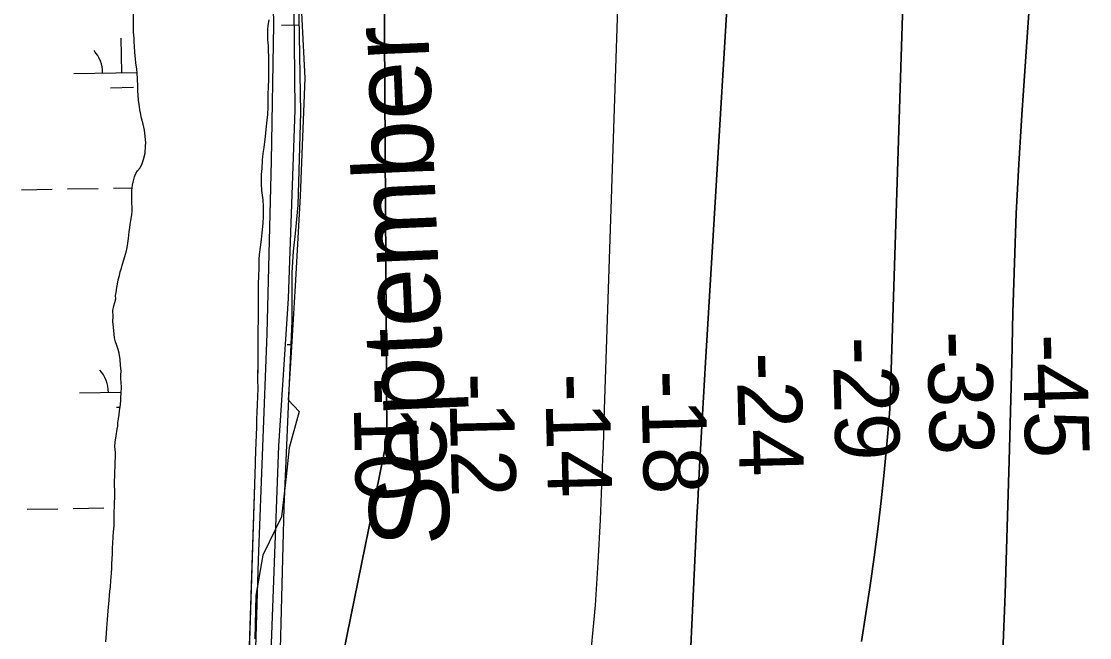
# Model space of a CAD drawing. Extents: x 3925854 to 3964121, y 224593 to 250589.
# Drawn here: x 3942489 to 3943602, y 239849 to 240491 of the extents above; entities that cross this region are included whole.
import ezdxf

# ---------------------------------------------------------------- set-up
doc = ezdxf.new("R2010")
doc.units = 0
for name, color, linetype in [('V-RIVR-EDGE', 7, 'Continuous'), ('V-RIVR-IDEN', 7, 'Continuous'), ('V-RIVR-JETY', 7, 'Continuous'), ('V-RIVR-RANG', 7, 'Continuous'), ('V-TOPO-DPTH', 7, 'Continuous'), ('V-TOPO-MINR', 7, 'Continuous'), ('V-TOPO-SHOR', 7, 'Continuous'), ('V-WETL-SWMP', 7, 'Continuous')]:
    doc.layers.add(name, color=color, linetype=linetype)

msp = doc.modelspace()

# ---------------------------------------------------------------- linework, layer by layer
at = {"layer": 'V-RIVR-EDGE'}
msp.add_lwpolyline([(3942781.233, 241173.826), (3942770.996, 241115.474), (3942773.043, 241052.004), (3942781.233, 241003.889), (3942775.091, 240945.538), (3942767.925, 240925.063), (3942763.83, 240896.399), (3942762.806, 240867.736), (3942765.877, 240813.479), (3942777.138, 240788.91), (3942776.115, 240597.475), (3942781.233, 240493.057), (3942784.304, 240431.634), (3942779.186, 240308.789), (3942774.067, 240215.631), (3942769.972, 240146.018), (3942766.901, 240096.88), (3942778.162, 240084.595), (3942767.925, 240046.718), (3942764.854, 240017.03), (3942759.735, 239975.058), (3942740.285, 239935.133), (3942733.119, 239893.161), (3942732.095, 239848.118)], dxfattribs=at)
at = {"layer": 'V-RIVR-JETY'}
for points in [[(3942501.881, 238496.007), (3942530.957, 238578.48), (3942555.82, 238617.728), (3942596.956, 238684.087), (3942673.397, 238798.99), (3942694.77, 238864.612), (3942700.089, 238923.816), (3942705.303, 239063.915), (3942714.359, 239211.498), (3942718.996, 239386.408), (3942726.512, 239566.929), (3942728.732, 239690.128), (3942735.923, 239929.912), (3942744.955, 240165.915), (3942749.64, 240345.527), (3942752.055, 240487.535), (3942748.285, 240668.175), (3942752.491, 240801.701), (3942752.37, 240880.714), (3942745.499, 240943.807), (3942747.22, 241019.038), (3942753.828, 241112.093), (3942757.154, 241251.271)], [(3942538.571, 238553.806), (3942560.622, 238594.024), (3942630.365, 238697.71), (3942697.234, 238796.723), (3942709.735, 238822.929), (3942715.631, 238847.327), (3942722.113, 238928.151), (3942724.245, 239042.886), (3942729.685, 239204.617), (3942737.78, 239350.33), (3942741.958, 239481.033), (3942746.566, 239653.121), (3942749.476, 239843.095), (3942757.257, 240049.011), (3942767.313, 240202.23), (3942774.055, 240398.75), (3942772.697, 240539.858), (3942769.602, 240695.094), (3942767.962, 240808.926), (3942767.018, 240899.237), (3942767.151, 241002.704), (3942769.979, 241093.915), (3942774.399, 241248.132)]]:
    msp.add_lwpolyline(points, dxfattribs=at)
at = {"layer": 'V-TOPO-DPTH'}
for points in [[(3942983.62, 238887.801), (3942658.91, 239021.11), (3942869.48, 240055.28), (3942865.529, 240782.275), (3942865.271, 240811.75), (3942864.883, 240841.222), (3942864.3, 240870.691), (3942863.587, 240900.157), (3942843.55, 241628.53), (3943150.608, 241695.11)], [(3943571.432, 241621.688), (3943574.45, 241120.853), (3943574.275, 241081.301), (3943573.548, 241041.766), (3943571.995, 241002.255), (3943569.89, 240962.759), (3943564.953, 240885.365), (3943564.898, 240884.579), (3943564.764, 240883.009), (3943564.409, 240879.085), (3943531.043, 240393.786), (3943527.862, 240342.338), (3943525.153, 240290.868), (3943523.154, 240239.366), (3943521.627, 240187.843), (3943520.452, 240136.144), (3943519.837, 240110.454), (3943519.18, 240084.766), (3943518.462, 240059.079), (3943517.702, 240033.393), (3943513.436, 239894.857), (3943509.884, 239799.938)], [(3943509.884, 239799.938), (3943513.436, 239894.857), (3943517.702, 240033.393), (3943518.462, 240059.079), (3943519.18, 240084.766), (3943519.837, 240110.454), (3943520.452, 240136.144), (3943521.627, 240187.843), (3943523.154, 240239.366), (3943525.153, 240290.868), (3943527.862, 240342.338), (3943531.043, 240393.786), (3943564.409, 240879.085), (3943564.764, 240883.009), (3943564.898, 240884.579), (3943564.953, 240885.365), (3943569.89, 240962.759), (3943571.995, 241002.255), (3943573.548, 241041.766), (3943574.275, 241081.301), (3943574.45, 241120.853), (3943571.432, 241621.688)], [(3943413.452, 240714.869), (3943394.296, 240106.295), (3943393.795, 240094.248), (3943393.132, 240082.211), (3943392.226, 240070.19), (3943391.157, 240058.18), (3943387.482, 240021.108), (3943384.342, 239991.683), (3943380.909, 239962.294), (3943377.036, 239932.96), (3943372.87, 239903.663), (3943368.385, 239874.409), (3943363.768, 239845.176)], [(3943363.768, 239845.176), (3943368.385, 239874.409), (3943372.87, 239903.663), (3943377.036, 239932.96), (3943380.909, 239962.294), (3943384.342, 239991.683), (3943387.482, 240021.108), (3943391.157, 240058.18), (3943392.226, 240070.19), (3943393.132, 240082.211), (3943393.795, 240094.248), (3943394.296, 240106.295), (3943413.452, 240714.869)], [(3943224.301, 240515.774), (3943201.362, 240135.797), (3943199.237, 240099.673), (3943197.185, 240063.546), (3943195.244, 240027.412), (3943193.376, 239991.275), (3943192.522, 239974.242), (3943190.327, 239929.583), (3943188.192, 239884.921), (3943186.145, 239840.255)], [(3943186.145, 239840.255), (3943188.192, 239884.921), (3943190.327, 239929.583), (3943192.522, 239974.242), (3943193.376, 239991.275), (3943195.244, 240027.412), (3943197.185, 240063.546), (3943199.237, 240099.673), (3943201.362, 240135.797), (3943224.301, 240515.774)]]:
    msp.add_lwpolyline(points, dxfattribs=at)
at = {"layer": 'V-TOPO-MINR'}
for points in [[(3942843.55, 241628.53), (3942863.587, 240900.157), (3942864.3, 240870.691), (3942864.883, 240841.222), (3942865.271, 240811.75), (3942865.529, 240782.275), (3942869.48, 240055.28), (3942658.91, 239021.11)], [(3943571.432, 241621.688), (3943574.45, 241120.853), (3943574.275, 241081.301), (3943573.548, 241041.766), (3943571.995, 241002.255), (3943569.89, 240962.759), (3943564.953, 240885.365), (3943564.898, 240884.579), (3943564.764, 240883.009), (3943564.409, 240879.085), (3943531.043, 240393.786), (3943527.862, 240342.338), (3943525.153, 240290.868), (3943523.154, 240239.366), (3943521.627, 240187.843), (3943520.452, 240136.144), (3943519.837, 240110.454), (3943519.18, 240084.766), (3943518.462, 240059.079), (3943517.702, 240033.393), (3943513.436, 239894.857), (3943509.884, 239799.938)], [(3943413.452, 240714.869), (3943394.296, 240106.295), (3943393.795, 240094.248), (3943393.132, 240082.211), (3943392.226, 240070.19), (3943391.157, 240058.18), (3943387.482, 240021.108), (3943384.342, 239991.683), (3943380.909, 239962.294), (3943377.036, 239932.96), (3943372.87, 239903.663), (3943368.385, 239874.409), (3943363.768, 239845.176)], [(3943114.557, 240651.144), (3943096.096, 240086.809), (3943095.66, 240073.897), (3943095.207, 240060.985), (3943094.729, 240048.075), (3943094.232, 240035.165), (3943091.739, 239971.982), (3943089.435, 239927.526), (3943086.4, 239883.128), (3943082.27, 239838.819)], [(3943224.301, 240515.774), (3943201.362, 240135.797), (3943199.237, 240099.673), (3943197.185, 240063.546), (3943195.244, 240027.412), (3943193.376, 239991.275), (3943192.522, 239974.242), (3943190.327, 239929.583), (3943188.192, 239884.921), (3943186.145, 239840.255)]]:
    msp.add_lwpolyline(points, dxfattribs=at)
at = {"layer": 'V-TOPO-SHOR'}
for points in [[(3942586.212, 240016.745), (3942586.439, 240022.637), (3942586.482, 240026.678), (3942586.712, 240032.568), (3942587.089, 240036.437), (3942586.976, 240041.825), (3942586.505, 240045.03), (3942586.37, 240048.231), (3942586.585, 240052.776), (3942587.664, 240059.331), (3942588.745, 240066.223), (3942589.284, 240069.418), (3942589.487, 240072.783), (3942590.038, 240077.153), (3942590.754, 240081.525), (3942591.131, 240085.224), (3942592.213, 240092.118), (3942592.596, 240096.492), (3942592.626, 240099.521), (3942593.005, 240103.56), (3942593.245, 240110.46), (3942592.784, 240114.674), (3942592.495, 240119.393), (3942592.532, 240122.928), (3942592.739, 240126.631), (3942592.301, 240133.033), (3942591.688, 240138.933), (3942590.746, 240145.509), (3942589.775, 240149.392), (3942588.469, 240153.277), (3942586.996, 240157.334), (3942585.86, 240161.387), (3942585.563, 240165.262), (3942584.797, 240172.512), (3942584.352, 240178.41), (3942584.574, 240183.626), (3942584.131, 240189.693), (3942585.36, 240194.565), (3942586.411, 240198.257), (3942587.289, 240201.952), (3942587.16, 240205.659), (3942587.529, 240208.686), (3942588.424, 240213.728), (3942588.967, 240217.427), (3942589.855, 240221.963), (3942591.078, 240226.327), (3942591.961, 240230.192), (3942593.179, 240234.052), (3942593.884, 240237.075), (3942595.797, 240242.781), (3942597.542, 240248.655), (3942598.416, 240251.845), (3942599.297, 240255.542), (3942599.848, 240260.08), (3942600.571, 240264.789), (3942601.316, 240271.684), (3942602.039, 240276.391), (3942602.406, 240279.418), (3942602.952, 240283.454), (3942603.858, 240289.506), (3942604.406, 240293.711), (3942604.439, 240296.91), (3942603.993, 240302.47), (3942604.056, 240308.7), (3942604.12, 240314.76), (3942604.683, 240320.31), (3942605.389, 240323.503), (3942606.794, 240329.045), (3942608.175, 240332.397), (3942610.059, 240335.41), (3942612.617, 240338.582), (3942614.851, 240342.936), (3942616.072, 240346.965), (3942617.827, 240353.85), (3942618.411, 240361.422), (3942618.441, 240364.453), (3942618.304, 240367.484), (3942618.011, 240371.528), (3942617.231, 240377.599), (3942615.781, 240383.843), (3942614.161, 240390.089), (3942612.873, 240395.66), (3942612.402, 240398.863), (3942611.619, 240404.765), (3942610.987, 240408.644), (3942610.71, 240414.541), (3942610.413, 240418.249), (3942610.133, 240423.64), (3942610.04, 240431.049), (3942609.43, 240437.118), (3942609.135, 240441.162), (3942608.193, 240447.739), (3942607.732, 240451.951), (3942607.128, 240458.693), (3942606.69, 240465.097), (3942606.565, 240469.308), (3942606.272, 240473.521), (3942605.83, 240479.585), (3942605.871, 240483.628), (3942605.764, 240489.522), (3942605.83, 240495.752)], [(3942746.593, 240492.371), (3942745.69, 240486.487), (3942745.311, 240482.45), (3942745.247, 240476.22), (3942745.37, 240471.841), (3942745.976, 240465.437), (3942746.093, 240460.385), (3942746.368, 240454.489), (3942746.271, 240445.228), (3942746.206, 240438.83), (3942746.275, 240429.401), (3942745.878, 240423.511), (3942745.618, 240414.59), (3942745.563, 240409.371), (3942745.483, 240401.626), (3942745.233, 240393.882), (3942744.668, 240387.996), (3942743.728, 240378.408), (3942742.978, 240371.174), (3942741.514, 240359.74), (3942740.605, 240353.352), (3942739.857, 240346.287), (3942739.265, 240337.876), (3942738.862, 240331.48), (3942738.761, 240321.715), (3942739.196, 240314.977), (3942740.273, 240305.03), (3942740.705, 240298.122), (3942740.766, 240287.849), (3942740.357, 240280.784), (3942739.411, 240270.689), (3942738.835, 240263.959), (3942737.739, 240255.72), (3942736.652, 240248.325), (3942736.431, 240243.107), (3942736.179, 240235.195), (3942736.064, 240224.083), (3942735.675, 240219.036), (3942735.093, 240130.475), (3942735.038, 240125.254), (3942734.966, 240118.353), (3942735.196, 240107.91), (3942734.958, 240101.176), (3942734.518, 240091.247), (3942734.282, 240084.851), (3942734.018, 240075.592), (3942733.785, 240069.197), (3942733.516, 240059.604), (3942733.279, 240052.87), (3942732.839, 240042.939), (3942732.566, 240033.008), (3942732.537, 240030.11), (3942720.692, 239671.78)], [(3942577.019, 239844.756), (3942577.617, 239853.675), (3942578.012, 239859.395), (3942578.772, 239867.806), (3942578.995, 239873.025), (3942579.751, 239880.93), (3942580.5, 239888.331), (3942580.885, 239893.042), (3942581.27, 239897.584), (3942581.821, 239901.957), (3942582.225, 239908.351), (3942582.433, 239912.389), (3942582.808, 239916.09), (3942583.04, 239921.98), (3942583.079, 239925.853), (3942583.646, 239931.741), (3942583.859, 239936.115), (3942583.928, 239942.851), (3942584.141, 239947.058), (3942584.553, 239954.461), (3942584.772, 239959.344), (3942585.514, 239965.734), (3942585.581, 239972.299), (3942585.626, 239976.676), (3942585.669, 239980.887), (3942586.048, 239984.923), (3942586.108, 239990.648), (3942586.312, 239994.012), (3942586.194, 239998.899), (3942586.228, 240002.266), (3942586.116, 240007.486), (3942586.003, 240013.044), (3942586.212, 240016.745)]]:
    msp.add_lwpolyline(points, dxfattribs=at)
at = {"layer": 'V-WETL-SWMP'}
for p, q in [((3942780.056, 240396.129), (3942776.847, 240592.444)), ((3942605.764, 240489.521), (3942605.918, 240504.337)), ((3942605.871, 240483.627), (3942605.764, 240489.521)), ((3942605.829, 240479.586), (3942605.871, 240483.627)), ((3942745.69, 240486.487), (3942745.311, 240482.45)), ((3942746.593, 240492.371), (3942745.69, 240486.487)), ((3942759.796, 240486.97), (3942778.566, 240487.312)), ((3942593.604, 240437.511), (3942592.95, 240473.505)), ((3942606.272, 240473.52), (3942605.829, 240479.586)), ((3942606.565, 240469.308), (3942606.272, 240473.52)), ((3942745.311, 240482.45), (3942745.247, 240476.221)), ((3942745.247, 240476.221), (3942745.37, 240471.841)), ((3942745.37, 240471.841), (3942745.977, 240465.437)), ((3942606.689, 240465.097), (3942606.565, 240469.308)), ((3942607.128, 240458.694), (3942606.689, 240465.097)), ((3942745.977, 240465.437), (3942746.093, 240460.384)), ((3942607.732, 240451.952), (3942607.128, 240458.694)), ((3942608.193, 240447.738), (3942607.732, 240451.952)), ((3942746.093, 240460.384), (3942746.368, 240454.488)), ((3942746.368, 240454.488), (3942746.206, 240438.83)), ((3942609.135, 240441.162), (3942608.193, 240447.738)), ((3942609.43, 240437.117), (3942609.135, 240441.162)), ((3942746.206, 240438.83), (3942746.276, 240429.4)), ((3942543.612, 240436.602), (3942609.38, 240437.798)), ((3942610.041, 240431.049), (3942609.43, 240437.117)), ((3942610.132, 240423.64), (3942610.041, 240431.049)), ((3942746.276, 240429.4), (3942745.878, 240423.511)), ((3942581.887, 240421.864), (3942605.883, 240422.301)), ((3942610.413, 240418.249), (3942610.132, 240423.64)), ((3942610.711, 240414.541), (3942610.413, 240418.249)), ((3942745.878, 240423.511), (3942745.618, 240414.59)), ((3942610.987, 240408.645), (3942610.711, 240414.541)), ((3942611.62, 240404.766), (3942610.987, 240408.645)), ((3942745.618, 240414.59), (3942745.483, 240401.626)), ((3942612.401, 240398.864), (3942611.62, 240404.766)), ((3942612.873, 240395.66), (3942612.401, 240398.864)), ((3942614.162, 240390.09), (3942612.873, 240395.66)), ((3942745.234, 240393.883), (3942744.668, 240387.996)), ((3942745.483, 240401.626), (3942745.234, 240393.883)), ((3942777.238, 240299.53), (3942780.056, 240396.129)), ((3942615.781, 240383.843), (3942614.162, 240390.09)), ((3942617.232, 240377.598), (3942615.781, 240383.843)), ((3942744.668, 240387.996), (3942743.727, 240378.408)), ((3942618.011, 240371.529), (3942617.232, 240377.598)), ((3942618.305, 240367.484), (3942618.011, 240371.529)), ((3942743.727, 240378.408), (3942742.978, 240371.175)), ((3942617.827, 240353.851), (3942618.411, 240361.422)), ((3942618.442, 240364.452), (3942618.305, 240367.484)), ((3942618.411, 240361.422), (3942618.442, 240364.452)), ((3942742.978, 240371.175), (3942741.513, 240359.741)), ((3942616.072, 240346.965), (3942617.827, 240353.851)), ((3942740.604, 240353.352), (3942739.858, 240346.287)), ((3942741.513, 240359.741), (3942740.604, 240353.352)), ((3942610.059, 240335.41), (3942612.617, 240338.582)), ((3942612.617, 240338.582), (3942614.851, 240342.937)), ((3942614.851, 240342.937), (3942616.072, 240346.965)), ((3942739.858, 240346.287), (3942739.265, 240337.875)), ((3942605.389, 240323.503), (3942606.794, 240329.045)), ((3942606.794, 240329.045), (3942608.175, 240332.398)), ((3942608.175, 240332.398), (3942610.059, 240335.41)), ((3942738.862, 240331.48), (3942738.761, 240321.715)), ((3942739.265, 240337.875), (3942738.862, 240331.48)), ((3942488.961, 240315.517), (3942520.955, 240316.099)), ((3942536.953, 240316.39), (3942568.948, 240316.972)), ((3942584.945, 240317.263), (3942604.409, 240317.617)), ((3942604.12, 240314.76), (3942604.682, 240320.311)), ((3942604.682, 240320.311), (3942605.389, 240323.503)), ((3942738.761, 240321.715), (3942739.196, 240314.976)), ((3942603.992, 240302.47), (3942604.12, 240314.76)), ((3942739.196, 240314.976), (3942740.272, 240305.03)), ((3942740.272, 240305.03), (3942740.705, 240298.122)), ((3942603.858, 240289.506), (3942604.406, 240293.71)), ((3942604.44, 240296.909), (3942603.992, 240302.47)), ((3942604.406, 240293.71), (3942604.44, 240296.909)), ((3942740.705, 240298.122), (3942740.767, 240287.85)), ((3942774.512, 240270.106), (3942777.238, 240299.53)), ((3942602.406, 240279.418), (3942602.953, 240283.454)), ((3942602.953, 240283.454), (3942603.858, 240289.506)), ((3942740.767, 240287.85), (3942740.357, 240280.783)), ((3942600.57, 240264.788), (3942601.315, 240271.684)), ((3942601.315, 240271.684), (3942602.038, 240276.391)), ((3942602.038, 240276.391), (3942602.406, 240279.418)), ((3942740.357, 240280.783), (3942739.41, 240270.69)), ((3942599.848, 240260.081), (3942600.57, 240264.788)), ((3942738.835, 240263.96), (3942737.739, 240255.721)), ((3942739.41, 240270.69), (3942738.835, 240263.96)), ((3942772.506, 240251.77), (3942774.512, 240270.106)), ((3942597.541, 240248.655), (3942598.416, 240251.846)), ((3942598.416, 240251.846), (3942599.296, 240255.541)), ((3942599.296, 240255.541), (3942599.848, 240260.081)), ((3942737.739, 240255.721), (3942736.652, 240248.324)), ((3942771.06, 240228.989), (3942772.506, 240251.77)), ((3942593.884, 240237.075), (3942595.796, 240242.78)), ((3942595.796, 240242.78), (3942597.541, 240248.655)), ((3942736.43, 240243.106), (3942736.179, 240235.195)), ((3942736.652, 240248.324), (3942736.43, 240243.106)), ((3942591.079, 240226.328), (3942591.961, 240230.192)), ((3942591.961, 240230.192), (3942593.18, 240234.052)), ((3942593.18, 240234.052), (3942593.884, 240237.075)), ((3942736.179, 240235.195), (3942736.064, 240224.083)), ((3942771.144, 240178.758), (3942771.06, 240228.989)), ((3942588.423, 240213.727), (3942588.966, 240217.426)), ((3942588.966, 240217.426), (3942589.855, 240221.963)), ((3942589.855, 240221.963), (3942591.079, 240226.328)), ((3942735.675, 240219.036), (3942735.093, 240130.474)), ((3942736.064, 240224.083), (3942735.675, 240219.036)), ((3942587.16, 240205.658), (3942587.528, 240208.685)), ((3942587.29, 240201.952), (3942587.16, 240205.658)), ((3942587.528, 240208.685), (3942588.423, 240213.727)), ((3942584.132, 240189.693), (3942585.361, 240194.564)), ((3942585.361, 240194.564), (3942586.41, 240198.257)), ((3942586.41, 240198.257), (3942587.29, 240201.952)), ((3942584.574, 240183.627), (3942584.132, 240189.693)), ((3942584.352, 240178.41), (3942584.574, 240183.627)), ((3942584.796, 240172.512), (3942584.352, 240178.41)), ((3942585.562, 240165.263), (3942584.796, 240172.512)), ((3942762.678, 239984.985), (3942771.144, 240178.758)), ((3942585.859, 240161.388), (3942585.562, 240165.263)), ((3942586.996, 240157.335), (3942585.859, 240161.388)), ((3942588.469, 240153.278), (3942586.996, 240157.335)), ((3942589.776, 240149.392), (3942588.469, 240153.278)), ((3942590.746, 240145.509), (3942589.776, 240149.392)), ((3942765.845, 240154.35), (3942770.081, 240154.427)), ((3942591.688, 240138.933), (3942590.746, 240145.509)), ((3942592.3, 240133.033), (3942591.688, 240138.933)), ((3942592.739, 240126.63), (3942592.3, 240133.033)), ((3942735.093, 240130.474), (3942734.967, 240118.352)), ((3942592.495, 240119.392), (3942592.532, 240122.928)), ((3942592.783, 240114.675), (3942592.495, 240119.392)), ((3942592.532, 240122.928), (3942592.739, 240126.63)), ((3942734.967, 240118.352), (3942735.196, 240107.91)), ((3942549.661, 240103.982), (3942593.047, 240104.771)), ((3942593.245, 240110.46), (3942592.783, 240114.675)), ((3942593.005, 240103.559), (3942593.245, 240110.46)), ((3942735.196, 240107.91), (3942734.958, 240101.177)), ((3942592.212, 240092.118), (3942592.595, 240096.492)), ((3942592.595, 240096.492), (3942592.626, 240099.522)), ((3942592.626, 240099.522), (3942593.005, 240103.559)), ((3942734.958, 240101.177), (3942734.518, 240091.248)), ((3942587.935, 240089.244), (3942591.772, 240089.314)), ((3942590.755, 240081.525), (3942591.131, 240085.225)), ((3942591.131, 240085.225), (3942592.212, 240092.118)), ((3942734.283, 240084.852), (3942734.019, 240075.593)), ((3942734.518, 240091.248), (3942734.283, 240084.852)), ((3942589.283, 240069.417), (3942589.486, 240072.782)), ((3942589.486, 240072.782), (3942590.037, 240077.154)), ((3942590.037, 240077.154), (3942590.755, 240081.525)), ((3942734.019, 240075.593), (3942733.784, 240069.197)), ((3942587.663, 240059.331), (3942588.745, 240066.223)), ((3942588.745, 240066.223), (3942589.283, 240069.417)), ((3942733.784, 240069.197), (3942733.516, 240059.603)), ((3942586.369, 240048.231), (3942586.584, 240052.775)), ((3942586.584, 240052.775), (3942587.663, 240059.331)), ((3942733.278, 240052.87), (3942732.838, 240042.94)), ((3942733.516, 240059.603), (3942733.278, 240052.87)), ((3942586.504, 240045.031), (3942586.369, 240048.231)), ((3942586.976, 240041.826), (3942586.504, 240045.031)), ((3942587.089, 240036.437), (3942586.976, 240041.826)), ((3942732.838, 240042.94), (3942732.567, 240033.008)), ((3942586.44, 240022.637), (3942586.482, 240026.677)), ((3942586.482, 240026.677), (3942586.712, 240032.568)), ((3942586.712, 240032.568), (3942587.089, 240036.437)), ((3942732.537, 240030.11), (3942720.692, 239671.781)), ((3942732.567, 240033.008), (3942732.537, 240030.11)), ((3942586.004, 240013.044), (3942586.211, 240016.746)), ((3942586.211, 240016.746), (3942586.44, 240022.637)), ((3942586.115, 240007.486), (3942586.004, 240013.044)), ((3942586.229, 240002.265), (3942586.115, 240007.486)), ((3942586.108, 239990.648), (3942586.312, 239994.013)), ((3942586.194, 239998.898), (3942586.229, 240002.265)), ((3942586.312, 239994.013), (3942586.194, 239998.898)), ((3942495.009, 239982.897), (3942527.004, 239983.479)), ((3942543.001, 239983.77), (3942574.996, 239984.352)), ((3942585.67, 239980.886), (3942586.049, 239984.924)), ((3942586.049, 239984.924), (3942586.108, 239990.648)), ((3942757.865, 239793.191), (3942762.678, 239984.985)), ((3942585.513, 239965.734), (3942585.67, 239980.886)), ((3942584.773, 239959.343), (3942585.513, 239965.734)), ((3942584.141, 239947.058), (3942584.554, 239954.462)), ((3942584.554, 239954.462), (3942584.773, 239959.343)), ((3942583.859, 239936.116), (3942583.929, 239942.851)), ((3942583.929, 239942.851), (3942584.141, 239947.058)), ((3942583.079, 239925.853), (3942583.645, 239931.741)), ((3942583.645, 239931.741), (3942583.859, 239936.116)), ((3942582.434, 239912.39), (3942582.809, 239916.09)), ((3942582.809, 239916.09), (3942583.039, 239921.981)), ((3942583.039, 239921.981), (3942583.079, 239925.853)), ((3942581.821, 239901.956), (3942582.224, 239908.351)), ((3942582.224, 239908.351), (3942582.434, 239912.39)), ((3942580.886, 239893.042), (3942581.27, 239897.584)), ((3942581.27, 239897.584), (3942581.821, 239901.956)), ((3942579.75, 239880.93), (3942580.501, 239888.331)), ((3942580.501, 239888.331), (3942580.886, 239893.042)), ((3942578.772, 239867.807), (3942578.995, 239873.024)), ((3942578.995, 239873.024), (3942579.75, 239880.93)), ((3942578.012, 239859.396), (3942578.772, 239867.807)), ((3942577.018, 239844.757), (3942577.616, 239853.675)), ((3942577.616, 239853.675), (3942578.012, 239859.396))]:
    msp.add_line(p, q, dxfattribs=at)
for centre in [(3942538.362, 240436.981), (3942544.41, 240104.361)]:
    msp.add_arc(centre, 35.246, 0.269879, 41.813537, dxfattribs=at)

# ---------------------------------------------------------------- texts
at = {"layer": 'V-RIVR-IDEN'}
msp.add_text('September', height=82.9998, rotation=92.478685, dxfattribs=at).set_placement((3942935.899, 239945.856))
at = {"layer": 'V-RIVR-RANG'}
for s, p in [('-33', (3943432.259, 240168.04)), ('-45', (3943531.471, 240164.798)), ('-29', (3943333.879, 240162.065)), ('-24', (3943233.813, 240145.755)), ('-10', (3942834.341, 240119.833)), ('-12', (3942934.262, 240124.203)), ('-14', (3943034.303, 240123.828)), ('-18', (3943134.251, 240127.144))]:
    msp.add_text(s, height=67, rotation=271.447, dxfattribs=at).set_placement(p)

doc.saveas('drawing.dxf')
